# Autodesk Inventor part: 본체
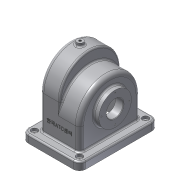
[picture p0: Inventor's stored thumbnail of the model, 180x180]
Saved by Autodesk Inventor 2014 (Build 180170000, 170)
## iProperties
Created: 2017-11
Part Number: 본체
Material: 알루미늄 6061
Document SubType Name: Modeling
Designer: user
Density: 2.71 g/cm^3
Appearance: 알루미늄 - 평지
Mass: 1079.2 g
Surface Area: 1187.1 cm^2
Volume: 398.23 cm^3
Author: user
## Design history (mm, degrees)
sketch "스케치1"
  geometry: L1 (55, 75)-(-55, 75); L2 (-55, 75)-(-55, -75); L3 (-55, -75)-(55, -75); L4 (55, -75)-(55, 75); L5 (55, 75)-(-55, -75); L6 (-55, 75)-(55, -75); 1 further point
  constraints: 12 end point, 2 midpoint, 2 parallel, 1 horizontal, 1 perpendicular
  dimensions: "d0" = 110 distance of L2.end L3.end; "d1" = 150 distance of L1.end L2.end
extrude "돌출1" new body sketch "스케치1" distance "d2" = 15; taper "d3" = 0 deg
sketch "스케치3"
  geometry: L1 (15, -75)-(15, 75) reference; L2 (0, -75)-(0, 75) reference; L3 (80, 58)-(15, 58); L4 (80, -58)-(15, -58); L5 (15, 58)-(15, -58); A1 r 58 centre (80, 0) between (80, -58) and (80, 58); 1 further point
  constraints: 6 end point, 2 perpendicular, 2 point on circle, 2 point on line, 2 tangent, 1 centre point, 1 collinear
  dimensions: "d4" = 116 diameter of A1; "d5" = 80 distance from line of L2 A1.centre
extrude "돌출2" join sketch "스케치3" distance "d6" = 38; taper "d7" = 0 deg
sketch "스케치4"
  geometry: L1 (-75, 0)-(75, 0) reference; C1 r 37.5 at (0, 65); A1 r 58 centre (0, 80) between (58, 80) and (-58, 80) reference; 1 further point
  constraints: 1 centre point, 1 vertical alignment
  dimensions: "d8" = 75 diameter of C1; "d9" = 65 distance from line of L1 C1.centre
extrude "돌출3" join sketch "스케치4" distance "d10" = 9; taper "d11" = 0 deg
sketch "스케치5"
  geometry: L1 (-58, 15)-(-58, 80) reference; L2 (58, 15)-(-58, 15) reference; L3 (58, 80)-(58, 15) reference; L4 (-75, 0)-(75, 0) reference; L5 (-58, 57)-(-58, 15); L6 (58, 57)-(58, 15); L7 (-58, 15)-(58, 15); A1 r 58 centre (0, 80) between (58, 80) and (-58, 80) reference; A2 r 58 centre (0, 57) between (58, 57) and (-58, 57); 1 further point
  constraints: 6 end point, 2 point on circle, 2 point on line, 1 centre point, 1 collinear, 1 parallel, 1 perpendicular, 1 tangent, 1 vertical alignment
  dimensions: "d13" = 57 distance from line of L4 A2.centre
extrude "돌출4" join sketch "스케치5" distance "d14" = 38; taper "d15" = 0 deg
sketch "스케치6"
  geometry: L1 (-75, 0)-(75, 0) reference; C1 r 31 at (0, 65); A1 r 58 centre (0, 57) between (58, 57) and (-58, 57) reference; 1 further point
  constraints: 1 centre point, 1 vertical alignment
  dimensions: "d16" = 62 diameter of C1; "d17" = 65 distance from line of L1 C1.centre
extrude "돌출5" join sketch "스케치6" distance "d18" = 10; taper "d19" = 0 deg
node "작업 평면1"
sketch "스케치7"
  geometry: L1 (-53, 80)-(-53, 0); L2 (-53, 0)-(53, 0); L3 (53, 0)-(53, 80); L4 (75, 0)-(-75, 0) reference; A1 r 58 centre (0, 80) between (58, 80) and (-58, 80) reference; A2 r 53 centre (0, 80) between (53, 80) and (-53, 80); 1 further point
  constraints: 6 end point, 2 point on circle, 2 tangent, 1 centre point, 1 collinear, 1 parallel, 1 perpendicular, 1 vertical
  dimensions: "d21" = 5 radial gap between concentric circles of A2 A1
extrude "돌출6" cut sketch "스케치7" distance "d22" = 28; taper "d23" = 0 deg
node "작업 평면2"
sketch "스케치9"
  geometry: L1 (-53, 0)-(53, 0) reference; L2 (-53, 57)-(-53, 0); L3 (53, 57)-(53, 0); L4 (-53, 0)-(53, 0); A1 r 58 centre (0, 57) between (58, 57) and (-58, 57) reference; A2 r 53 centre (0, 57) between (53, 57) and (-53, 57); 1 further point
  constraints: 6 end point, 2 point on circle, 2 tangent, 1 centre point, 1 collinear
  dimensions: "d25" = 5 radial gap between concentric circles of A2 A1
extrude "돌출7" cut sketch "스케치9" stored distance "d26" = 28; taper "d27" = 0 deg
fillet "모깎기1" dims "d28" = 3
hole "구멍1" diameter "d31" = 32; stored, may be unused: countersink angle "d35" = 90 deg, drill point angle "d37" = 118 deg; dims "d29" = 10, "d30" = 10, "d32" = 6, "d33" = 4, "d34" = 2, "d36" = 8
chamfer "모따기1" distance "d38" = 1; stored, may be unused: second distance "d39" = 2, angle "d40" = 45 deg
node "작업 평면3"
sketch "스케치10"
  geometry: L1 (0, -58)-(-38, -58) reference; L2 (55, -75)-(-55, -75) reference; L3 (-38, 58)-(-38, -58) reference; C1 r 6 at (-19, 0); 1 further point
  constraints: 1 centre point
  dimensions: "d42" = 12 diameter of C1; "d44" = 75 distance from line of L2 C1.centre; "d45" = 19 distance from line of L3 C1.centre
extrude "돌출8" join sketch "스케치10" stored distance "d46" = 28; taper "d47" = 0 deg
hole "구멍2" diameter "d50" = 4.459; stored, may be unused: countersink angle "d54" = 90 deg, drill point angle "d56" = 118 deg; dims "d51" = 15, "d52" = 4, "d53" = 2, "d55" = 8, "d107" = 10, "d108" = 10
fillet "모깎기2" dims "d58" = 3
fillet "모깎기3" dims "d59" = 8
fillet "모깎기4" dims "d60" = 12
hole "구멍3" diameter "d63" = 5; stored, may be unused: countersink angle "d67" = 90 deg, drill point angle "d69" = 118 deg; dims "d61" = 10, "d62" = 10, "d64" = 5, "d65" = 12, "d66" = 5, "d68" = 8
hole "구멍4" diameter "d72" = 5; stored, may be unused: countersink angle "d76" = 90 deg, drill point angle "d78" = 118 deg; dims "d70" = 10, "d71" = 10, "d73" = 5, "d74" = 12, "d75" = 5, "d77" = 8
fillet "모깎기5" dims "d79" = 3
sketch "스케치11"
  geometry: C1 r 37.5 at (0, 0) reference; 2 further points
  constraints: 1 vertical alignment
  dimensions: "d80" = 29 distance of C1.centre point (0, 29)
hole "구멍5" sketch "스케치11" at (0, 29) diameter "d81" = 2.459; stored, may be unused: countersink angle "d85" = 90 deg, drill point angle "d87" = 118 deg; dims "d82" = 6, "d83" = 12, "d84" = 5, "d86" = 8
sketch "스케치12"
  geometry: C1 r 31 at (0, 0) reference; 2 further points
  constraints: 1 vertical alignment
  dimensions: "d91" = 26 distance of point (0, 26) C1.centre
hole "구멍6" sketch "스케치12" at (0, 26) diameter "d92" = 2.459; stored, may be unused: countersink angle "d96" = 90 deg, drill point angle "d98" = 118 deg; dims "d93" = 6, "d94" = 12, "d95" = 5, "d97" = 8
sketch "스케치13"
  geometry: L1 (-40, -57)-(46, -57) reference; L2 (-35, 23)-(-35, -39) reference; 2 further points
  constraints: 1 other
  dimensions: "d102" = 40 distance from line of L1 point (3, -17); "d103" = 38 distance from line of L2 point (3, -17)
feature "엠보싱1" sketch "스케치13" dims "d0" = 110, "d1" = 150, "d8" = 75, "d9" = 65, "d104" = 0.5, "d105" = 0
fillet "모깎기7" dims "d109" = 3
node "솔리드1"
mirror "대칭1"
pattern_circular "원형 패턴1" dims angle "d89" = 360 deg
pattern_circular "원형 패턴2" dims angle "d100" = 360 deg
other parameters: "d12" = 116, "d20" = -5, "d24" = -5, "d41" = -144
